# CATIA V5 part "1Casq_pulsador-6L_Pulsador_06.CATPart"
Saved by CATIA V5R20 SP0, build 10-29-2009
Part number: 1Casq_pulsador-6L_Pulsador_06
Revision: ANY
Definition: UNKNOWN
Nomenclature: 1Casq_pulsador-6L_Pulsador_06
Source: Unknown
Bounding box of the stored display mesh (mm): x -6.63 to 6.63, y 0 to 15.3, z -6.8 to 6.8
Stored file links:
  C:\Users\Utente\Desktop\IO LAVORO\3D X SITO CF\CUMSA\3D files BA\BA 061418\1Casq_pulsador-6L_Pulsador_06.CATPart
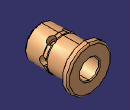
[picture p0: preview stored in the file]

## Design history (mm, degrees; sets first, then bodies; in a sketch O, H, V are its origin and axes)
Body1 "MatrizC1" (main body)
  Solid1: solid without history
